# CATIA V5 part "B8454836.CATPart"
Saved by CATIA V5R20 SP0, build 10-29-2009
Part number: B8454836
Revision: 1
Definition: design
Nomenclature: B8454836
Source: made
Description: NOT SPECIFIED
Bounding box of the stored display mesh (mm): x -36.5 to 36.5, y -36.5 to 36.5, z -22 to 27
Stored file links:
  C:\Users\Utente\Desktop\3D files B845\B8454836.CATPart
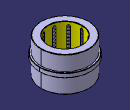
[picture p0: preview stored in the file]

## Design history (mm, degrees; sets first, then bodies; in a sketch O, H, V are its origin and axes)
Body1 "MANIFOLD_SOLID_BREP #38" (main body)
  Solid1: solid without history
Body2 "MANIFOLD_SOLID_BREP #2472"
  Solid2: solid without history
Body3 "MANIFOLD_SOLID_BREP #2510"
  Solid3: solid without history
Body4 "MANIFOLD_SOLID_BREP #2548"
  Solid4: solid without history
Body5 "MANIFOLD_SOLID_BREP #2586"
  Solid5: solid without history
Body6 "MANIFOLD_SOLID_BREP #2624"
  Solid6: solid without history
Body7 "MANIFOLD_SOLID_BREP #2662"
  Solid7: solid without history
Body8 "MANIFOLD_SOLID_BREP #2700"
  Solid8: solid without history
Body9 "MANIFOLD_SOLID_BREP #2738"
  Solid9: solid without history
Body10 "MANIFOLD_SOLID_BREP #2776"
  Solid10: solid without history
Body11 "MANIFOLD_SOLID_BREP #2814"
  Solid11: solid without history
Body12 "MANIFOLD_SOLID_BREP #2852"
  Solid12: solid without history
Body13 "MANIFOLD_SOLID_BREP #2890"
  Solid13: solid without history
Body14 "MANIFOLD_SOLID_BREP #2928"
  Solid14: solid without history
Body15 "MANIFOLD_SOLID_BREP #2966"
  Solid15: solid without history
Body16 "MANIFOLD_SOLID_BREP #3004"
  Solid16: solid without history
Body17 "MANIFOLD_SOLID_BREP #3042"
  Solid17: solid without history
Body18 "MANIFOLD_SOLID_BREP #3080"
  Solid18: solid without history
Body19 "MANIFOLD_SOLID_BREP #3118"
  Solid19: solid without history
Body20 "MANIFOLD_SOLID_BREP #3156"
  Solid20: solid without history
Body21 "MANIFOLD_SOLID_BREP #3194"
  Solid21: solid without history
Body22 "MANIFOLD_SOLID_BREP #3232"
  Solid22: solid without history
Body23 "MANIFOLD_SOLID_BREP #3270"
  Solid23: solid without history
Body24 "MANIFOLD_SOLID_BREP #3308"
  Solid24: solid without history
Body25 "MANIFOLD_SOLID_BREP #3346"
  Solid25: solid without history
Body26 "MANIFOLD_SOLID_BREP #3384"
  Solid26: solid without history
Body27 "MANIFOLD_SOLID_BREP #3422"
  Solid27: solid without history
Body28 "MANIFOLD_SOLID_BREP #3460"
  Solid28: solid without history
Body29 "MANIFOLD_SOLID_BREP #3498"
  Solid29: solid without history
Body30 "MANIFOLD_SOLID_BREP #3536"
  Solid30: solid without history
Body31 "MANIFOLD_SOLID_BREP #3574"
  Solid31: solid without history
Body32 "MANIFOLD_SOLID_BREP #3612"
  Solid32: solid without history
Body33 "MANIFOLD_SOLID_BREP #3650"
  Solid33: solid without history
Body34 "MANIFOLD_SOLID_BREP #3688"
  Solid34: solid without history
Body35 "MANIFOLD_SOLID_BREP #3726"
  Solid35: solid without history
Body36 "MANIFOLD_SOLID_BREP #3764"
  Solid36: solid without history
Body37 "MANIFOLD_SOLID_BREP #3802"
  Solid37: solid without history
Body38 "MANIFOLD_SOLID_BREP #3840"
  Solid38: solid without history
Body39 "MANIFOLD_SOLID_BREP #3878"
  Solid39: solid without history
Body40 "MANIFOLD_SOLID_BREP #3916"
  Solid40: solid without history
Body41 "MANIFOLD_SOLID_BREP #3954"
  Solid41: solid without history
Body42 "MANIFOLD_SOLID_BREP #3992"
  Solid42: solid without history
Body43 "MANIFOLD_SOLID_BREP #4030"
  Solid43: solid without history
Body44 "MANIFOLD_SOLID_BREP #4068"
  Solid44: solid without history
Body45 "MANIFOLD_SOLID_BREP #4106"
  Solid45: solid without history
Body46 "MANIFOLD_SOLID_BREP #4144"
  Solid46: solid without history
Body47 "MANIFOLD_SOLID_BREP #4182"
  Solid47: solid without history
Body48 "MANIFOLD_SOLID_BREP #4220"
  Solid48: solid without history
Body49 "MANIFOLD_SOLID_BREP #4258"
  Solid49: solid without history
Body50 "MANIFOLD_SOLID_BREP #4296"
  Solid50: solid without history
Body51 "MANIFOLD_SOLID_BREP #4334"
  Solid51: solid without history
Body52 "MANIFOLD_SOLID_BREP #4372"
  Solid52: solid without history
Body53 "MANIFOLD_SOLID_BREP #4410"
  Solid53: solid without history
Body54 "MANIFOLD_SOLID_BREP #4448"
  Solid54: solid without history
Body55 "MANIFOLD_SOLID_BREP #4486"
  Solid55: solid without history
Body56 "MANIFOLD_SOLID_BREP #4524"
  Solid56: solid without history
Body57 "MANIFOLD_SOLID_BREP #4562"
  Solid57: solid without history
Body58 "MANIFOLD_SOLID_BREP #4600"
  Solid58: solid without history
Body59 "MANIFOLD_SOLID_BREP #4638"
  Solid59: solid without history
Body60 "MANIFOLD_SOLID_BREP #4676"
  Solid60: solid without history
Body61 "MANIFOLD_SOLID_BREP #4714"
  Solid61: solid without history
Body62 "MANIFOLD_SOLID_BREP #4752"
  Solid62: solid without history
Body63 "MANIFOLD_SOLID_BREP #4790"
  Solid63: solid without history
Body64 "MANIFOLD_SOLID_BREP #4828"
  Solid64: solid without history
Body65 "MANIFOLD_SOLID_BREP #4866"
  Solid65: solid without history
Body66 "MANIFOLD_SOLID_BREP #4904"
  Solid66: solid without history
Body67 "MANIFOLD_SOLID_BREP #4942"
  Solid67: solid without history
Body68 "MANIFOLD_SOLID_BREP #4980"
  Solid68: solid without history
Body69 "MANIFOLD_SOLID_BREP #5018"
  Solid69: solid without history
Body70 "MANIFOLD_SOLID_BREP #5056"
  Solid70: solid without history
Body71 "MANIFOLD_SOLID_BREP #5094"
  Solid71: solid without history
Body72 "MANIFOLD_SOLID_BREP #5132"
  Solid72: solid without history
Body73 "MANIFOLD_SOLID_BREP #5170"
  Solid73: solid without history
Body74 "MANIFOLD_SOLID_BREP #5208"
  Solid74: solid without history
Body75 "MANIFOLD_SOLID_BREP #5246"
  Solid75: solid without history
Body76 "MANIFOLD_SOLID_BREP #5284"
  Solid76: solid without history
Body77 "MANIFOLD_SOLID_BREP #5322"
  Solid77: solid without history
Body78 "MANIFOLD_SOLID_BREP #5360"
  Solid78: solid without history
Body79 "MANIFOLD_SOLID_BREP #5398"
  Solid79: solid without history
Body80 "MANIFOLD_SOLID_BREP #5436"
  Solid80: solid without history
Body81 "MANIFOLD_SOLID_BREP #5474"
  Solid81: solid without history
Body82 "MANIFOLD_SOLID_BREP #5512"
  Solid82: solid without history
Body83 "MANIFOLD_SOLID_BREP #5550"
  Solid83: solid without history
Body84 "MANIFOLD_SOLID_BREP #5588"
  Solid84: solid without history
Body85 "MANIFOLD_SOLID_BREP #5626"
  Solid85: solid without history
Body86 "MANIFOLD_SOLID_BREP #5664"
  Solid86: solid without history
Body87 "MANIFOLD_SOLID_BREP #5702"
  Solid87: solid without history
Body88 "MANIFOLD_SOLID_BREP #5740"
  Solid88: solid without history
Body89 "MANIFOLD_SOLID_BREP #5778"
  Solid89: solid without history
Body90 "MANIFOLD_SOLID_BREP #5816"
  Solid90: solid without history
Body91 "MANIFOLD_SOLID_BREP #5854"
  Solid91: solid without history
Body92 "MANIFOLD_SOLID_BREP #5892"
  Solid92: solid without history
Body93 "MANIFOLD_SOLID_BREP #5930"
  Solid93: solid without history
Body94 "MANIFOLD_SOLID_BREP #5968"
  Solid94: solid without history
Body95 "MANIFOLD_SOLID_BREP #6006"
  Solid95: solid without history
Body96 "MANIFOLD_SOLID_BREP #6044"
  Solid96: solid without history
Body97 "MANIFOLD_SOLID_BREP #6082"
  Solid97: solid without history
Body98 "MANIFOLD_SOLID_BREP #6120"
  Solid98: solid without history
Body99 "MANIFOLD_SOLID_BREP #6158"
  Solid99: solid without history
Body100 "MANIFOLD_SOLID_BREP #6196"
  Solid100: solid without history
Body101 "MANIFOLD_SOLID_BREP #6234"
  Solid101: solid without history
